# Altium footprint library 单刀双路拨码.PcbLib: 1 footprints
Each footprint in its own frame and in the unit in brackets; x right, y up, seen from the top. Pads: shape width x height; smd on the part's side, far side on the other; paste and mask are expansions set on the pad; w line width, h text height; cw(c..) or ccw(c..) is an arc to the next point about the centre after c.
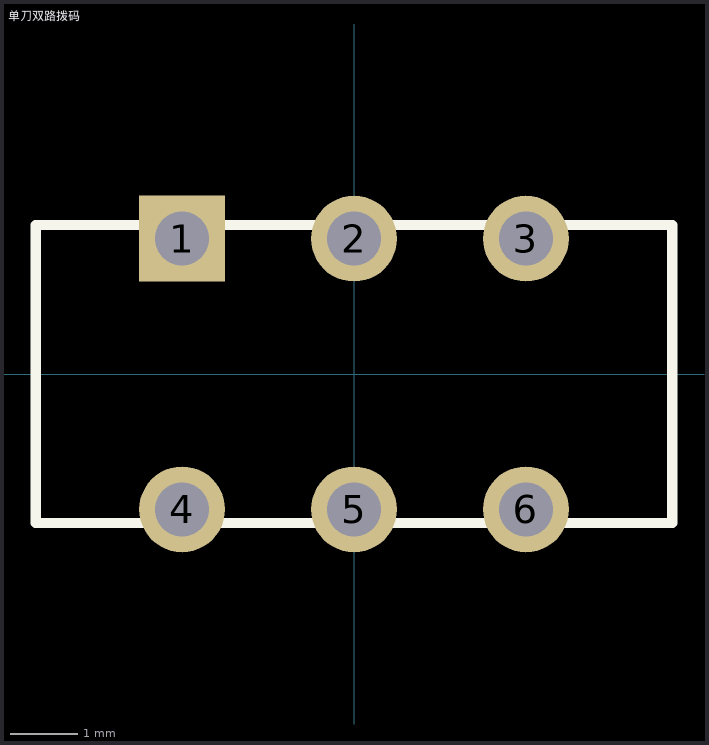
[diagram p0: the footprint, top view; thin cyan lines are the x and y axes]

## 单刀双路拨码 [mm] "单刀双路拨码"
pads (6):
  rect 1.27x1.27 hole 0.8: 1(-2.54,2)
  round 1.27 hole 0.8: 2(0,2) 3(2.54,2) 4(-2.54,-2) 5(0,-2) 6(2.54,-2)
Top Overlay:
  lines w0.152: -4.7,-2.2 -4.7,2.2 4.7,2.2 4.7,-2.2 -4.7,-2.2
